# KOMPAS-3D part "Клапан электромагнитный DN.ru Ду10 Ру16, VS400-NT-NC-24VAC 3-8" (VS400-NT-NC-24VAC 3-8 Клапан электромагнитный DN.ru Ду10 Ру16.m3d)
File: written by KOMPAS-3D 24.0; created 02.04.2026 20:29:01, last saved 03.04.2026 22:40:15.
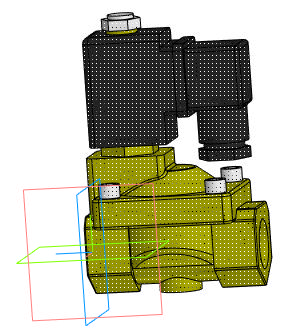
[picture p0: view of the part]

Document properties: Автор: artio; Полное имя файла: C:\Users\artio\OneDrive\Рабочий стол\Клапан электромагнитный DN.ru\VS400-NT-NC\VS400-NT-NC-24VAC 3-8 Клапан электромагнитный DN.ru Ду10 Ру16.m3d

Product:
- Body: Тело 1  | qty 1
    Масса: 1.030062
- Part/product: Клапан электромагнитный DN.ru Ду10 Ру16  | designation VS400-NT-NC-24VAC 3-8
    Масса: 0.797
    Раздел спецификации: Прочие изделия
    Примечание: D130-05630
    additional columns: ef56311e-7521-43dc-8291-0e6108b3d81d; VS400-ET-NC-220VAC 3-8; artio; c; Шероховатость не задана; Да

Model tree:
1. Операция без истории:1

Expressions: VS400-NT-NC-24VAC 3-8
